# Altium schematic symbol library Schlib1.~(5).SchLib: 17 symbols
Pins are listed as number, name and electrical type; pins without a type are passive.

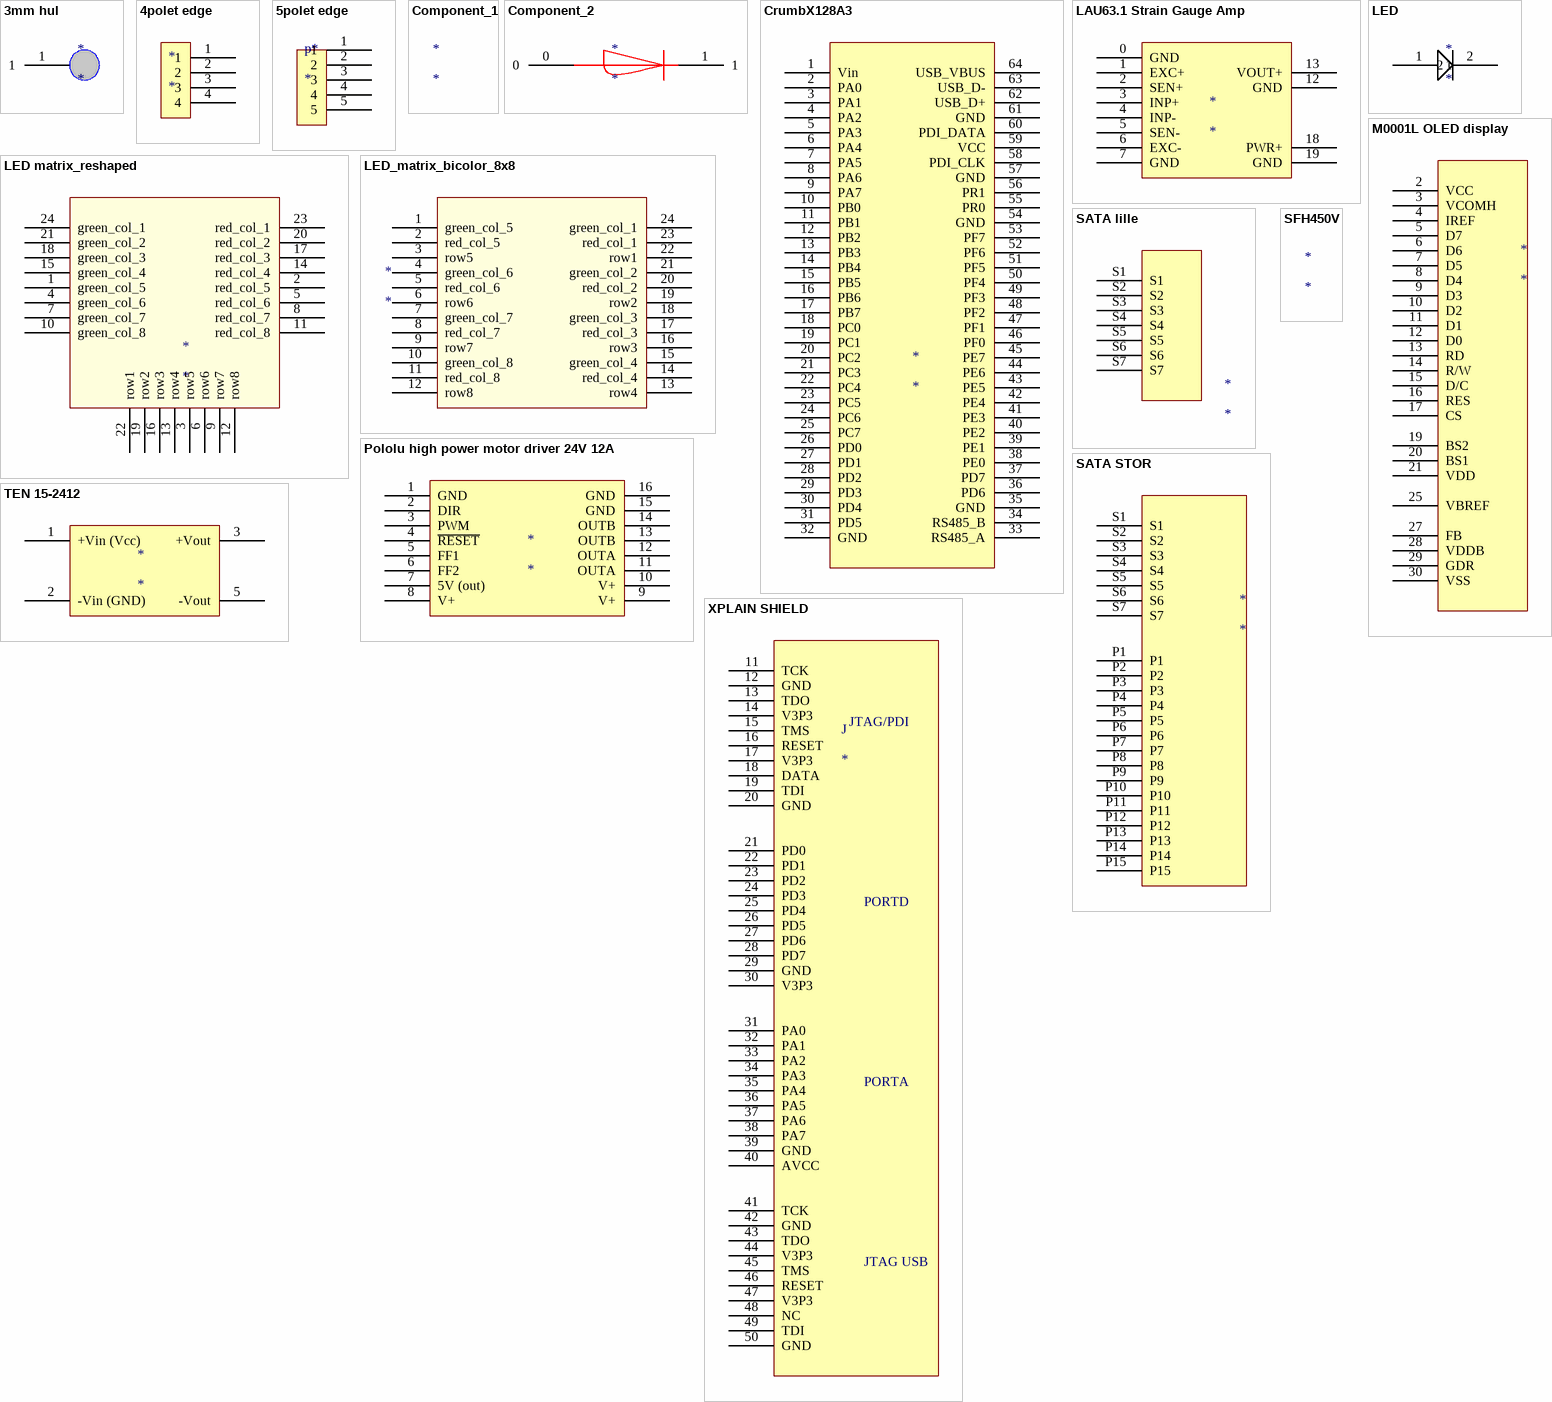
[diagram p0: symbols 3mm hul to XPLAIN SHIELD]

## 3mm hul
designator *
footprint 3mm_hul_DIY
pins: 1

## 4polet edge
designator *
footprint 4_polet_conn
pins: 1, 2, 3, 4

## 5polet edge
designator p*
footprint 4_polet_conn
pins: 1, 2, 3, 4, 5

## Component_1
designator *

## Component_2
designator *
footprint PCBComponent_1 - duplicate
pins: 0, 1

## CrumbX128A3
designator *
pins: 1 Vin, 2 PA0, 3 PA1, 4 PA2, 5 PA3, 6 PA4, 7 PA5, 8 PA6, 9 PA7, 10 PB0, 11 PB1, 12 PB2, 13 PB3, 14 PB4, 15 PB5, 16 PB6, 17 PB7, 18 PC0, 19 PC1, 20 PC2, 21 PC3, 22 PC4, 23 PC5, 24 PC6, 25 PC7, 26 PD0, 27 PD1, 28 PD2, 29 PD3, 30 PD4, 31 PD5, 32 GND, 33 RS485_A, 34 RS485_B, 35 GND, 36 PD6, 37 PD7, 38 PE0, 39 PE1, 40 PE2, 41 PE3, 42 PE4, 43 PE5, 44 PE6, 45 PE7, 46 PF0, 47 PF1, 48 PF2, 49 PF3, 50 PF4, 51 PF5, 52 PF6, 53 PF7, 54 GND, 55 PR0, 56 PR1, 57 GND, 58 PDI_CLK, 59 VCC, 60 PDI_DATA, 61 GND, 62 USB_D+, 63 USB_D-, 64 USB_VBUS

## LAU63.1 Strain Gauge Amp
designator *
footprint LAU63.1 Strain Gauge Amp
pins: 0 GND, 1 EXC+, 2 SEN+, 3 INP+, 4 INP-, 5 SEN-, 6 EXC-, 7 GND, 12 GND, 13 VOUT+, 18 PWR+, 19 GND

## LED
designator *
footprint 5mm5mm_LED_rectangular
pins: 1, 2

## LED matrix_reshaped
designator *
footprint LED_matrix_bicolor_8x8
pins: 1 green_col_5, 2 red_col_5, 3 row5, 4 green_col_6, 5 red_col_6, 6 row6, 7 green_col_7, 8 red_col_7, 9 row7, 10 green_col_8, 11 red_col_8, 12 row8, 13 row4, 14 red_col_4, 15 green_col_4, 16 row3, 17 red_col_3, 18 green_col_3, 19 row2, 20 red_col_2, 21 green_col_2, 22 row1, 23 red_col_1, 24 green_col_1

## LED_matrix_bicolor_8x8
designator *
footprint LED_matrix_bicolor_8x8
pins: 1 green_col_5, 2 red_col_5, 3 row5, 4 green_col_6, 5 red_col_6, 6 row6, 7 green_col_7, 8 red_col_7, 9 row7, 10 green_col_8, 11 red_col_8, 12 row8, 13 row4, 14 red_col_4, 15 green_col_4, 16 row3, 17 red_col_3, 18 green_col_3, 19 row2, 20 red_col_2, 21 green_col_2, 22 row1, 23 red_col_1, 24 green_col_1

## M0001L OLED display
designator *
footprint M0001L OLED DISPLAY
pins: 2 VCC, 3 VCOMH, 4 IREF, 5 D7, 6 D6, 7 D5, 8 D4, 9 D3, 10 D2, 11 D1, 12 D0, 13 RD, 14 R/W, 15 D/C, 16 RES, 17 CS, 19 BS2, 20 BS1, 21 VDD, 25 VBREF, 27 FB, 28 VDDB, 29 GDR, 30 VSS

## Pololu high power motor driver 24V 12A
designator *
footprint pololu hig power motor driver 24V 12A
pins: 1 GND, 2 DIR, 3 PWM, 4 ~{RESET}, 5 FF1, 6 FF2, 7 5V (out), 8 V+, 9 V+, 10 V+, 11 OUTA, 12 OUTA, 13 OUTB, 14 OUTB, 15 GND, 16 GND

## SATA lille
designator *
footprint pmr_sata -lille
pins: S1, S2, S3, S4, S5, S6, S7

## SATA STOR
designator *
footprint pmr_sata
pins: P1, P2, P3, P4, P5, P6, P7, P8, P9, P10, P11, P12, P13, P14, P15, S1, S2, S3, S4, S5, S6, S7

## SFH450V
designator *

## TEN 15-2412
designator *
footprint TEN 15-2412
pins: 1 +Vin (Vcc), 2 -Vin (GND), 3 +Vout, 5 -Vout

## XPLAIN SHIELD
designator J
footprint XPLAIN SHIELD
pins: 11 TCK, 12 GND, 13 TDO, 14 V3P3, 15 TMS, 16 RESET, 17 V3P3, 18 DATA, 19 TDI, 20 GND, 21 PD0, 22 PD1, 23 PD2, 24 PD3, 25 PD4, 26 PD5, 27 PD6, 28 PD7, 29 GND, 30 V3P3, 31 PA0, 32 PA1, 33 PA2, 34 PA3, 35 PA4, 36 PA5, 37 PA6, 38 PA7, 39 GND, 40 AVCC, 41 TCK, 42 GND, 43 TDO, 44 V3P3, 45 TMS, 46 RESET, 47 V3P3, 48 NC, 49 TDI, 50 GND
